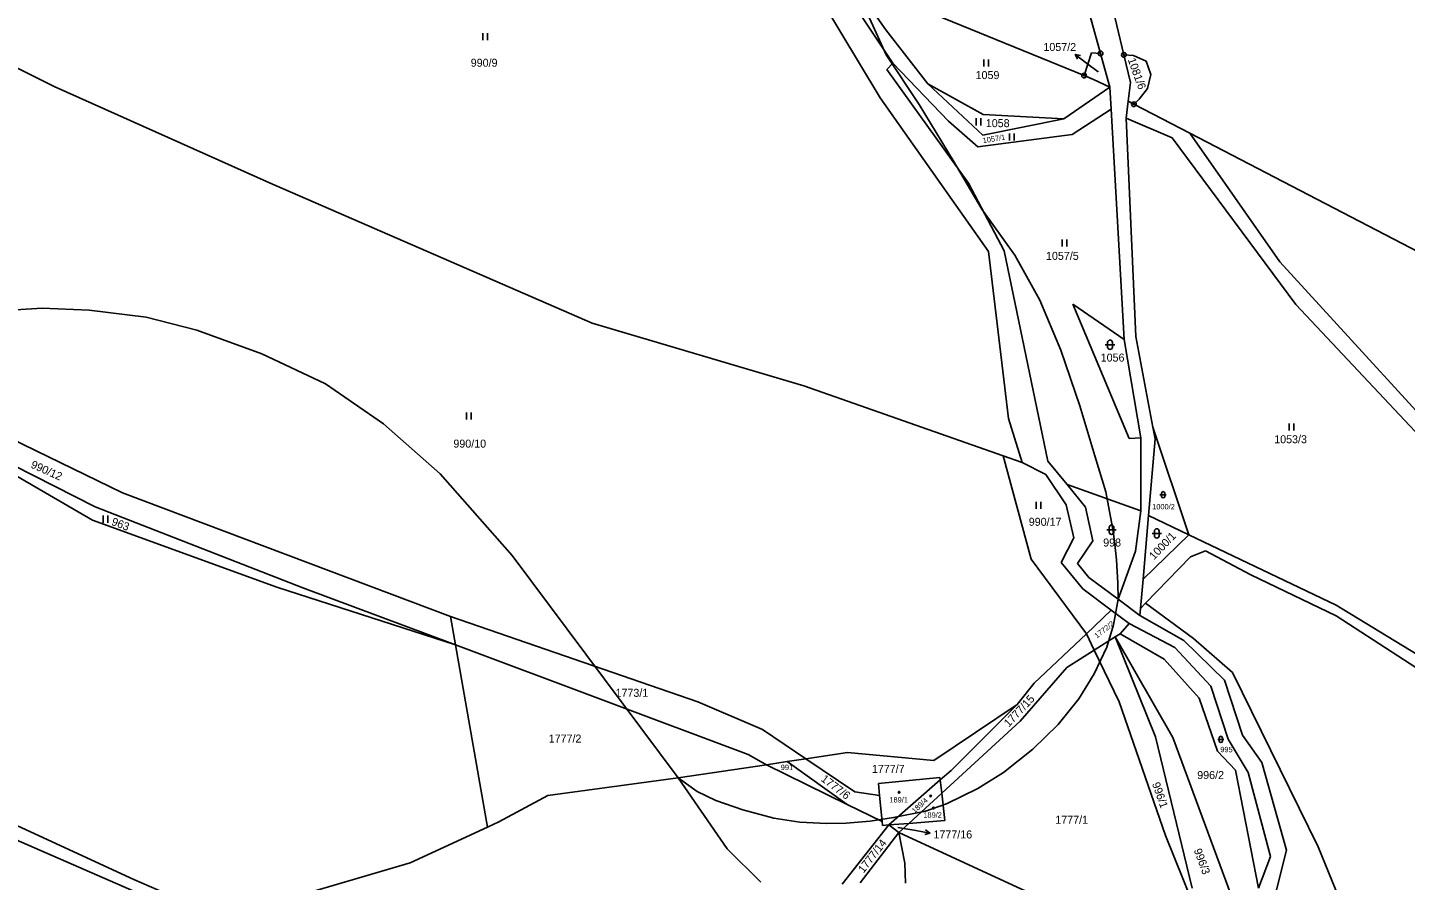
# Model space of a CAD drawing. Extents: x -546762 to -540209, y -1046851 to -1035694.
# Drawn here: x -543546.4 to -543253.7, y -1042005.7 to -1041824.4 of the extents above; entities that cross this region are included whole.
import ezdxf

# ---------------------------------------------------------------- set-up
doc = ezdxf.new("R2010")
doc.units = 0
for name, color, linetype in [('Vrstva 1', 7, 'Continuous'), ('Vrstva 16', 7, 'Continuous'), ('Vrstva 18', 7, 'Continuous'), ('Vrstva 19', 7, 'Continuous'), ('Vrstva 24', 7, 'Continuous'), ('Vrstva 25', 7, 'Continuous'), ('Vrstva 3', 7, 'Continuous'), ('Vrstva 37', 7, 'Continuous'), ('Vrstva 52', 7, 'Continuous'), ('Vrstva 6', 7, 'Continuous')]:
    doc.layers.add(name, color=color, linetype=linetype)

msp = doc.modelspace()

# ---------------------------------------------------------------- linework, layer by layer
at = {"layer": 'Vrstva 1'}
for p, q in [((-543366.93, -1041816.2), (-543321.94, -1041834.61)), ((-543339.12, -1041915.43), (-543381.5, -1041900.53)), ((-543339.12, -1041915.43), (-543333.2, -1041937.39)), ((-543335.07, -1041916.85), (-543339.12, -1041915.43)), ((-543333.2, -1041937.39), (-543321.46, -1041953.21)), ((-543315.32, -1041953.91), (-543303.1, -1041975.25)), ((-543303.1, -1041975.25), (-543290.65, -1042008.97))]:
    msp.add_line(p, q, dxfattribs=at)
for points in [[(-543328.5, -1041793.51), (-543318.45, -1041829.9)], [(-543362.55, -1041831.96), (-543375.34, -1041812.76)], [(-543378.01, -1041818.06), (-543365.29, -1041839.33)], [(-543316.46, -1041817.63), (-543313.5, -1041830.21)], [(-543560.44, -1041827.16), (-543540.76, -1041836.92)], [(-543320.4, -1041829.78), (-543321.94, -1041834.61)], [(-543320.4, -1041829.78), (-543318.45, -1041829.9)], [(-543318.45, -1041829.9), (-543316.46, -1041837.1)], [(-543363.86, -1041833.35), (-543362.55, -1041831.96)], [(-543313.5, -1041830.21), (-543312.12, -1041836.1)], [(-543313.5, -1041830.21), (-543311.48, -1041830.33)], [(-543311.48, -1041830.33), (-543308.75, -1041831.57)], [(-543308.75, -1041831.57), (-543307.76, -1041834.37)], [(-543346.53, -1041857.47), (-543363.86, -1041833.35)], [(-543321.94, -1041834.61), (-543319.97, -1041835.41)], [(-543319.97, -1041835.41), (-543316.46, -1041837.1)], [(-543307.76, -1041834.37), (-543308.46, -1041837.35)], [(-543495.05, -1041857.39), (-543540.76, -1041836.92)], [(-543316.46, -1041837.1), (-543316.2, -1041841.73)], [(-543312.58, -1041840.07), (-543312.12, -1041836.1)], [(-543308.46, -1041837.35), (-543310.23, -1041839.61)], [(-543365.29, -1041839.33), (-543342.29, -1041872.01)], [(-543316.2, -1041841.73), (-543313.4, -1041890.68)], [(-543313, -1041843.64), (-543312.58, -1041840.07)], [(-543312.58, -1041840.07), (-543311.35, -1041840.71)], [(-543310.23, -1041839.61), (-543311.35, -1041840.71)], [(-543311.35, -1041840.71), (-543299.5, -1041846.87)], [(-543310.93, -1041890.04), (-543313, -1041843.64)], [(-543299.5, -1041846.87), (-543227.4, -1041884.35)], [(-543426.49, -1041887.23), (-543495.05, -1041857.39)], [(-543338.92, -1041871.85), (-543346.53, -1041857.47)], [(-543338.01, -1041907.47), (-543342.29, -1041872.01)], [(-543338.92, -1041871.85), (-543329.62, -1041916.55)], [(-543313.4, -1041890.68), (-543324.32, -1041883.21)], [(-543324.32, -1041883.21), (-543312.37, -1041911.7)], [(-543381.5, -1041900.53), (-543426.49, -1041887.23)], [(-543313.4, -1041890.68), (-543309.86, -1041911.61)], [(-543310.93, -1041890.04), (-543307.33, -1041909.3)], [(-543526.25, -1041923.26), (-543579.18, -1041897.54)], [(-543532.07, -1041926.25), (-543575.35, -1041904.3)], [(-543338.01, -1041907.47), (-543335.07, -1041916.85)], [(-543312.37, -1041911.7), (-543309.86, -1041911.61)], [(-543309.86, -1041911.61), (-543309.86, -1041927.09)], [(-543308.25, -1041928.11), (-543306.86, -1041911.82)], [(-543307.33, -1041909.3), (-543306.86, -1041911.82)], [(-543299.66, -1041932.21), (-543307.33, -1041909.3)], [(-543335.07, -1041916.85), (-543330.09, -1041919.39)], [(-543325.56, -1041921.52), (-543329.62, -1041916.55)], [(-543330.09, -1041919.39), (-543325.73, -1041925.82)], [(-543456.59, -1041949.59), (-543526.25, -1041923.26)], [(-543321.67, -1041926.29), (-543325.56, -1041921.52)], [(-543325.56, -1041921.52), (-543309.86, -1041927.09)], [(-543487.98, -1041943.45), (-543532.07, -1041926.25)], [(-543325.73, -1041925.82), (-543324.1, -1041932.86)], [(-543321.67, -1041926.29), (-543320.07, -1041933.45)], [(-543309.86, -1041927.09), (-543311, -1041935.69)], [(-543309.41, -1041941.66), (-543308.25, -1041928.11)], [(-543309.41, -1041941.66), (-543299.66, -1041932.21)], [(-543268.4, -1041947.13), (-543299.66, -1041932.21)], [(-543324.1, -1041932.86), (-543326.8, -1041938.1)], [(-543320.07, -1041933.45), (-543323.35, -1041938.27)], [(-543326.8, -1041938.1), (-543322.19, -1041943.7)], [(-543323.35, -1041938.27), (-543320.93, -1041941.27)], [(-543311, -1041935.69), (-543314.72, -1041945.89)], [(-543308.88, -1041946.76), (-543299.36, -1041936.86)], [(-543299.36, -1041936.86), (-543296.14, -1041935.62)], [(-543286.52, -1041940.72), (-543296.14, -1041935.62)], [(-543314.72, -1041945.89), (-543320.93, -1041941.27)], [(-543268.39, -1041949.44), (-543286.52, -1041940.72)], [(-543455.54, -1041955.59), (-543487.98, -1041943.45)], [(-543322.19, -1041943.7), (-543316.18, -1041948.2)], [(-543309.94, -1041947.86), (-543309.41, -1041941.66)], [(-543310.07, -1041949.35), (-543314.72, -1041945.89)], [(-543309.94, -1041947.86), (-543308.88, -1041946.76)], [(-543298.7, -1041954.23), (-543308.88, -1041946.76)], [(-543268.4, -1041947.13), (-543243.39, -1041962.39)], [(-543456.59, -1041949.59), (-543404, -1041967.71)], [(-543455.54, -1041955.59), (-543456.59, -1041949.59)], [(-543321.46, -1041953.21), (-543316.18, -1041948.2)], [(-543316.18, -1041948.2), (-543312.37, -1041951.07)], [(-543310.07, -1041949.35), (-543309.94, -1041947.86)], [(-543310.07, -1041949.35), (-543300.74, -1041954.64)], [(-543268.39, -1041949.44), (-543247.39, -1041963.02)], [(-543314.27, -1041953.26), (-543312.37, -1041951.07)], [(-543312.37, -1041951.07), (-543302.63, -1041956.18)], [(-543393.29, -1041978.88), (-543455.54, -1041955.59)], [(-543448.73, -1041994.31), (-543455.54, -1041955.59)], [(-543321.46, -1041953.21), (-543332.52, -1041963.7)], [(-543321.46, -1041953.21), (-543319.77, -1041956.7)], [(-543319.77, -1041956.7), (-543315.32, -1041953.91)], [(-543315.32, -1041953.91), (-543314.27, -1041953.26)], [(-543315.32, -1041953.91), (-543306.79, -1041975.13)], [(-543304.91, -1041958.64), (-543314.27, -1041953.26)], [(-543300.74, -1041954.64), (-543292.11, -1041963.08)], [(-543290.42, -1041961.49), (-543298.7, -1041954.23)], [(-543319.77, -1041956.7), (-543314.46, -1041967.68)], [(-543304.91, -1041958.64), (-543297.52, -1041966.91)], [(-543302.63, -1041956.18), (-543295.01, -1041964.35)], [(-543290.42, -1041961.49), (-543272.19, -1041998.52)], [(-543332.52, -1041963.7), (-543336.14, -1041968.26)], [(-543295.01, -1041964.35), (-543291.34, -1041975.65)], [(-543292.11, -1041963.08), (-543288.28, -1041974.78)], [(-543404, -1041967.71), (-543390.3, -1041973.58)], [(-543314.46, -1041967.68), (-543304.68, -1041996.12)], [(-543297.52, -1041966.91), (-543293.63, -1041978.2)], [(-543353.87, -1041980.13), (-543336.14, -1041968.26)], [(-543390.3, -1041973.58), (-543381.07, -1041979.8)], [(-543306.79, -1041975.13), (-543299, -1042007.27)], [(-543291.34, -1041975.65), (-543287.09, -1041982.7)], [(-543288.28, -1041974.78), (-543284.18, -1041980.61)], [(-543393.29, -1041978.88), (-543389.44, -1041981.05)], [(-543372.23, -1041978.48), (-543381.07, -1041979.8)], [(-543372.23, -1041978.48), (-543353.87, -1041980.13)], [(-543293.63, -1041978.2), (-543289.75, -1041982.19)], [(-543389.44, -1041981.05), (-543408.19, -1041983.86)], [(-543385.05, -1041980.39), (-543389.44, -1041981.05)], [(-543381.07, -1041979.8), (-543385.05, -1041980.39)], [(-543289.75, -1041982.19), (-543284.88, -1042007.29)], [(-543284.18, -1041980.61), (-543278.94, -1041999.23)], [(-543408.19, -1041983.86), (-543435.9, -1041987.59)], [(-543365.64, -1041985.03), (-543352.57, -1041983.8)], [(-543365.39, -1041987.6), (-543365.64, -1041985.03)], [(-543352.57, -1041983.8), (-543352.51, -1041984.3)], [(-543352.51, -1041984.3), (-543352.2, -1041987.12)], [(-543287.09, -1041982.7), (-543282.35, -1042000.54)], [(-543435.9, -1041987.59), (-543446.3, -1041993.2)], [(-543364.85, -1041993.14), (-543365.39, -1041987.6)], [(-543352.2, -1041987.12), (-543351.54, -1041992.94)], [(-543446.3, -1041993.2), (-543448.73, -1041994.31)], [(-543364.77, -1041993.94), (-543364.85, -1041993.14)], [(-543363.42, -1041993.84), (-543364.77, -1041993.94)], [(-543359.16, -1041993.52), (-543363.42, -1041993.84)], [(-543351.54, -1041992.94), (-543359.16, -1041993.52)], [(-543448.73, -1041994.31), (-543465.15, -1042001.89)], [(-543320.38, -1042014.35), (-543361.3, -1041995.48)], [(-543360.07, -1042002), (-543361.3, -1041995.48)], [(-543304.68, -1041996.12), (-543298.92, -1042010.35)], [(-543278.94, -1041999.23), (-543281.28, -1042008.47)], [(-543272.19, -1041998.52), (-543267.81, -1042009.28)], [(-543465.15, -1042001.89), (-543492.11, -1042009.87)], [(-543359.87, -1042006.23), (-543360.07, -1042002)], [(-543282.35, -1042000.54), (-543284.88, -1042007.29)]]:
    msp.add_lwpolyline(points, dxfattribs=at)
at = {"layer": 'Vrstva 16'}
for p, q in [((-543321.43, -1041831.95), (-543323.83, -1041830.15)), ((-543357.67, -1041995.07), (-543354.71, -1041995.57))]:
    msp.add_line(p, q, dxfattribs=at)
for points in [[(-543323.33, -1041831.15), (-543323.83, -1041830.15), (-543322.73, -1041830.35)], [(-543318.92, -1041833.84), (-543321.43, -1041831.95)], [(-543361.5, -1041994.43), (-543357.67, -1041995.07)], [(-543355.61, -1041994.91), (-543354.71, -1041995.57), (-543355.78, -1041995.89)]]:
    msp.add_lwpolyline(points, dxfattribs=at)
at = {"layer": 'Vrstva 24'}
for centre, radius in [((-543318.45, -1041829.9), 0.5), ((-543318.45, -1041829.9), 0.1), ((-543313.5, -1041830.21), 0.5), ((-543313.5, -1041830.21), 0.1), ((-543321.94, -1041834.61), 0.5), ((-543321.94, -1041834.61), 0.1), ((-543311.35, -1041840.71), 0.5), ((-543311.35, -1041840.71), 0.1)]:
    msp.add_circle(centre, radius, dxfattribs=at)
at = {"layer": 'Vrstva 25'}
for p, q in [((-543449.73, -1041827.08), (-543449.73, -1041825.58)), ((-543448.73, -1041827.08), (-543448.73, -1041825.58)), ((-543343.28, -1041832.67), (-543343.28, -1041831.17)), ((-543342.28, -1041832.67), (-543342.28, -1041831.17)), ((-543344.87, -1041845.19), (-543344.87, -1041843.69)), ((-543343.87, -1041845.19), (-543343.87, -1041843.69)), ((-543337.77, -1041848.43), (-543337.77, -1041846.93)), ((-543336.77, -1041848.43), (-543336.77, -1041846.93)), ((-543326.59, -1041870.95), (-543326.59, -1041869.45)), ((-543325.59, -1041870.95), (-543325.59, -1041869.45)), ((-543316.94, -1041892.31), (-543316.94, -1041891.31)), ((-543315.94, -1041891.31), (-543315.94, -1041892.31)), ((-543317.44, -1041891.81), (-543315.44, -1041891.81)), ((-543453.18, -1041907.71), (-543453.18, -1041906.21)), ((-543452.18, -1041907.71), (-543452.18, -1041906.21)), ((-543278.4, -1041910.04), (-543278.4, -1041908.54)), ((-543277.4, -1041910.04), (-543277.4, -1041908.54)), ((-543305.82, -1041923.69), (-543304.48, -1041923.69)), ((-543305.48, -1041924.03), (-543305.48, -1041923.35)), ((-543304.82, -1041923.35), (-543304.82, -1041924.03)), ((-543332.16, -1041926.68), (-543332.16, -1041925.18)), ((-543331.16, -1041926.68), (-543331.16, -1041925.18)), ((-543530.41, -1041929.62), (-543530.41, -1041928.12)), ((-543529.41, -1041929.62), (-543529.41, -1041928.12)), ((-543317.11, -1041931.11), (-543315.11, -1041931.11)), ((-543316.61, -1041931.61), (-543316.61, -1041930.61)), ((-543315.61, -1041930.61), (-543315.61, -1041931.61)), ((-543307.51, -1041931.9), (-543305.51, -1041931.9)), ((-543307.01, -1041932.4), (-543307.01, -1041931.4)), ((-543306.01, -1041931.4), (-543306.01, -1041932.4)), ((-543293.56, -1041975.69), (-543292.22, -1041975.69)), ((-543293.22, -1041976.03), (-543293.22, -1041975.35)), ((-543292.56, -1041975.35), (-543292.56, -1041976.03))]:
    msp.add_line(p, q, dxfattribs=at)
for centre in [(-543361.25, -1041986.92), (-543354.53, -1041987.72), (-543353.95, -1041990.27)]:
    msp.add_circle(centre, 0.175, dxfattribs=at)
for centre, radius, start, end in [((-543316.44, -1041891.31), 0.5, 0, 180), ((-543316.44, -1041892.31), 0.5, 180, 0), ((-543305.15, -1041923.35), 0.335, 0, 180), ((-543305.15, -1041924.03), 0.335, 180, 0), ((-543316.11, -1041930.61), 0.5, 0, 180), ((-543316.11, -1041931.61), 0.5, 180, 0), ((-543306.51, -1041931.4), 0.5, 0, 180), ((-543306.51, -1041932.4), 0.5, 180, 0), ((-543292.89, -1041975.35), 0.335, 0, 180), ((-543292.89, -1041976.03), 0.335, 180, 0)]:
    msp.add_arc(centre, radius, start, end, dxfattribs=at)
at = {"layer": 'Vrstva 3'}
for points in [[(-543365.64, -1041985.03), (-543352.57, -1041983.8)], [(-543365.39, -1041987.6), (-543365.64, -1041985.03)], [(-543352.57, -1041983.8), (-543352.51, -1041984.3)], [(-543352.51, -1041984.3), (-543352.2, -1041987.12)], [(-543364.85, -1041993.14), (-543365.39, -1041987.6)], [(-543352.2, -1041987.12), (-543351.54, -1041992.94)], [(-543364.77, -1041993.94), (-543364.85, -1041993.14)], [(-543363.42, -1041993.84), (-543364.77, -1041993.94)], [(-543359.16, -1041993.52), (-543363.42, -1041993.84)], [(-543351.54, -1041992.94), (-543359.16, -1041993.52)]]:
    msp.add_lwpolyline(points, dxfattribs=at)
at = {"layer": 'Vrstva 37'}
msp.add_circle((-543361.25, -1041986.92), 0.175, dxfattribs=at)
at = {"layer": 'Vrstva 52'}
for points in [[(-543370.35, -1041816.08), (-543363.99, -1041830.17), (-543356.99, -1041840.77), (-543349.79, -1041852.64), (-543343.64, -1041863.03), (-543336.65, -1041872.79), (-543331.35, -1041882.33), (-543326.9, -1041892.93), (-543322.87, -1041904.81), (-543319.69, -1041915.41), (-543317.36, -1041923.04), (-543315.88, -1041930.68), (-543315.49, -1041933.52), (-543315.08, -1041937.53), (-543314.8, -1041942.45), (-543314.72, -1041945.89), (-543315.68, -1041951.32), (-543317.13, -1041956.05), (-543319.8, -1041961.74), (-543323.07, -1041967.08), (-543327.43, -1041972.53), (-543332.87, -1041977.74), (-543339.05, -1041982.71), (-543344.5, -1041986.1), (-543351.16, -1041989.37), (-543355.64, -1041990.95), (-543362.43, -1041992.28), (-543367.39, -1041993.04), (-543372.51, -1041993.46), (-543376.66, -1041993.53), (-543382.34, -1041993.25), (-543387.87, -1041992.42), (-543394.45, -1041990.62), (-543400.19, -1041988.68), (-543404.14, -1041986.74), (-543408.19, -1041983.86)], [(-543661.16, -1042003.56), (-543654.93, -1041989.26), (-543646.67, -1041973.78), (-543637.98, -1041957.46), (-543626.17, -1041939.58), (-543615.15, -1041925.16), (-543606.25, -1041914.77), (-543599.26, -1041907.98), (-543590.36, -1041900.77), (-543579.76, -1041893.56), (-543571.71, -1041889.32), (-543562.81, -1041886.14), (-543553.69, -1041884.66), (-543543.31, -1041884.02), (-543533.35, -1041884.44)], [(-543533.35, -1041884.44), (-543521.27, -1041885.93), (-543510.46, -1041888.68), (-543496.68, -1041893.77), (-543483.12, -1041900.14), (-543470.82, -1041908.62), (-543458.74, -1041919.22), (-543443.48, -1041936.61), (-543408.19, -1041983.86)], [(-543408.19, -1041983.86), (-543397.78, -1041998.95), (-543390.63, -1042006.04)]]:
    msp.add_lwpolyline(points, dxfattribs=at)
at = {"layer": 'Vrstva 6'}
for points in [[(-543364.07, -1041824.9), (-543371.4, -1041814.37)], [(-543355.16, -1041836.37), (-543364.07, -1041824.9)], [(-543362.55, -1041831.96), (-543350.77, -1041844.31)], [(-543343.36, -1041842.87), (-543355.16, -1041836.37)], [(-543355.16, -1041836.37), (-543343.43, -1041847.29)], [(-543316.46, -1041837.1), (-543326.26, -1041843.81)], [(-543324.51, -1041847.14), (-543316.2, -1041841.73)], [(-543350.77, -1041844.31), (-543344.51, -1041849.74)], [(-543343.43, -1041847.29), (-543326.26, -1041843.81)], [(-543326.26, -1041843.81), (-543343.36, -1041842.87)], [(-543313, -1041843.64), (-543303.25, -1041847.81)], [(-543344.51, -1041849.74), (-543324.51, -1041847.14)], [(-543299.5, -1041846.87), (-543280.38, -1041874.22)], [(-543303.25, -1041847.81), (-543276.94, -1041883.25)], [(-543280.38, -1041874.22), (-543236.94, -1041921.67)], [(-543276.94, -1041883.25), (-543242.82, -1041919.56)], [(-543532.65, -1041929.12), (-543575.35, -1041904.3)], [(-543493.49, -1041943.36), (-543532.65, -1041929.12)], [(-543299.66, -1041932.21), (-543308.25, -1041928.11)], [(-543455.54, -1041955.59), (-543493.49, -1041943.36)], [(-543319.77, -1041956.7), (-543325.63, -1041960.37)], [(-543325.63, -1041960.37), (-543335.56, -1041971.83)], [(-543523.87, -1042005.44), (-543607.58, -1041966.86)], [(-543336.14, -1041968.26), (-543350.2, -1041982.28)], [(-543335.56, -1041971.83), (-543352.2, -1041987.12)], [(-543589.38, -1041979.37), (-543522.23, -1042008.65)], [(-543372.27, -1041989.49), (-543389.44, -1041981.05)], [(-543385.05, -1041980.39), (-543372.27, -1041989.49)], [(-543381.07, -1041979.8), (-543370.68, -1041986.81)], [(-543350.2, -1041982.28), (-543352.51, -1041984.3)], [(-543352.51, -1041984.3), (-543363.42, -1041993.84)], [(-543370.68, -1041986.81), (-543365.39, -1041987.6)], [(-543359.16, -1041993.52), (-543352.2, -1041987.12)], [(-543364.85, -1041993.14), (-543372.27, -1041989.49)], [(-543373.33, -1042006.43), (-543363.42, -1041993.84)], [(-543361.3, -1041995.48), (-543363.42, -1041993.84)], [(-543359.16, -1041993.52), (-543361.3, -1041995.48)], [(-543361.3, -1041995.48), (-543369.5, -1042006.13)], [(-543501.07, -1042015.4), (-543523.87, -1042005.44)]]:
    msp.add_lwpolyline(points, dxfattribs=at)

# ---------------------------------------------------------------- texts
at = {"layer": 'Vrstva 16'}
for s, p in [('1057/2', (-543330.59, -1041829.38)), ('1777/16', (-543353.95, -1041996.72))]:
    msp.add_text(s, height=1.7, dxfattribs=at).set_placement(p)
at = {"layer": 'Vrstva 18'}
for s, height, p in [('990/9', 1.7, (-543452.27, -1041832.73)), ('1059', 1.7, (-543345, -1041835.35)), ('1057/2', 0.1, (-543319.13, -1041833.84)), ('1058', 1.7, (-543342.83, -1041845.57)), ('1057/5', 1.7, (-543330.04, -1041873.77)), ('1056', 1.7, (-543318.42, -1041895.39)), ('990/10', 1.7, (-543455.96, -1041913.67)), ('1053/3', 1.7, (-543281.55, -1041912.74)), ('1000/2', 1.14, (-543307.48, -1041926.8)), ('990/17', 1.7, (-543333.7, -1041930.28)), ('998', 1.7, (-543317.89, -1041934.69)), ('1773/1', 1.7, (-543421.51, -1041966.63)), ('1777/2', 1.7, (-543435.71, -1041976.35)), ('995', 1.14, (-543293.01, -1041978.4)), ('991', 1.14, (-543386.4, -1041982.2)), ('1777/7', 1.7, (-543367.04, -1041982.8)), ('996/2', 1.7, (-543297.91, -1041984.1)), ('1777/1', 1.7, (-543328.06, -1041993.6)), ('1777/16', 0.1, (-543361.74, -1041994.43))]:
    msp.add_text(s, height=height, dxfattribs=at).set_placement(p)
for s, height, rotation, p in [('1081/6', 1.7, 289.9757, (-543312.7, -1041831.2)), ('1057/1', 1.14, 9.3878, (-543343.39, -1041848.99)), ('990/12', 1.7, 335.8468, (-543545.91, -1041917.86)), ('963', 1.7, 339.2446, (-543528.75, -1041930.05)), ('1000/1', 1.7, 46.1681, (-543307.09, -1041937.63)), ('1772/2', 1.14, 37.8171, (-543319.22, -1041954.27)), ('1777/15', 1.7, 46.8327, (-543337.94, -1041973.17)), ('1777/6', 1.7, 322.9578, (-543378, -1041984.38)), ('996/1', 1.7, 289.5059, (-543307.54, -1041985.1)), ('1777/14', 1.7, 52.2995, (-543368.81, -1042004.21)), ('996/3', 1.7, 290.265, (-543298.66, -1041999.22))]:
    msp.add_text(s, height=height, rotation=rotation, dxfattribs=at).set_placement(p)
at = {"layer": 'Vrstva 19'}
for s, p in [('189/1', (-543363.32, -1041989.08)), ('189/2', (-543356.11, -1041992.31))]:
    msp.add_text(s, height=1.14, dxfattribs=at).set_placement(p)
msp.add_text('189/4', height=1.14, rotation=41.9917, dxfattribs=at).set_placement((-543357.96, -1041991.44))

doc.saveas('drawing.dxf')
